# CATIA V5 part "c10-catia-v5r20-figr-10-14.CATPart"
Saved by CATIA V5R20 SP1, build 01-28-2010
Part number: Part1
Bounding box of the stored display mesh (mm): x -59.023 to 59.085, y -59.069 to 29.542, z 0 to 150
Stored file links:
  D:\v5_r20\psrt_files_downloaded\c10\c10-catia-v5r20-figr-10-14.CATPart
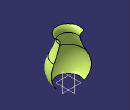
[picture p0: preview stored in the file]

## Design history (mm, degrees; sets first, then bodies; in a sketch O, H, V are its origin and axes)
Set1
  Sketch1 on yz-plane, origin (0, 0, 0), H (0, 1, 0), V (0, 0, 1)
    arc A1 centre (219.5293, 176.8574) radius 194.8379 from (50.3627, 80.1907) to (30.3627, 130.1907) cw
    arc A2 centre (-7.8186, 46.9443) radius 67.0103 from (50.3627, 80.1907) to (40, 0) cw
    arc A3 centre (47.0688, 134.312) radius 17.207 from (30.3627, 130.1907) to (40, 150) cw
    axis line L1 (0, 156.5671) -> (0, -24.1442)
    vertical: L1 V
  Revol1: Element1 Sketch1, Angle1 -60
Body1 (main body)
